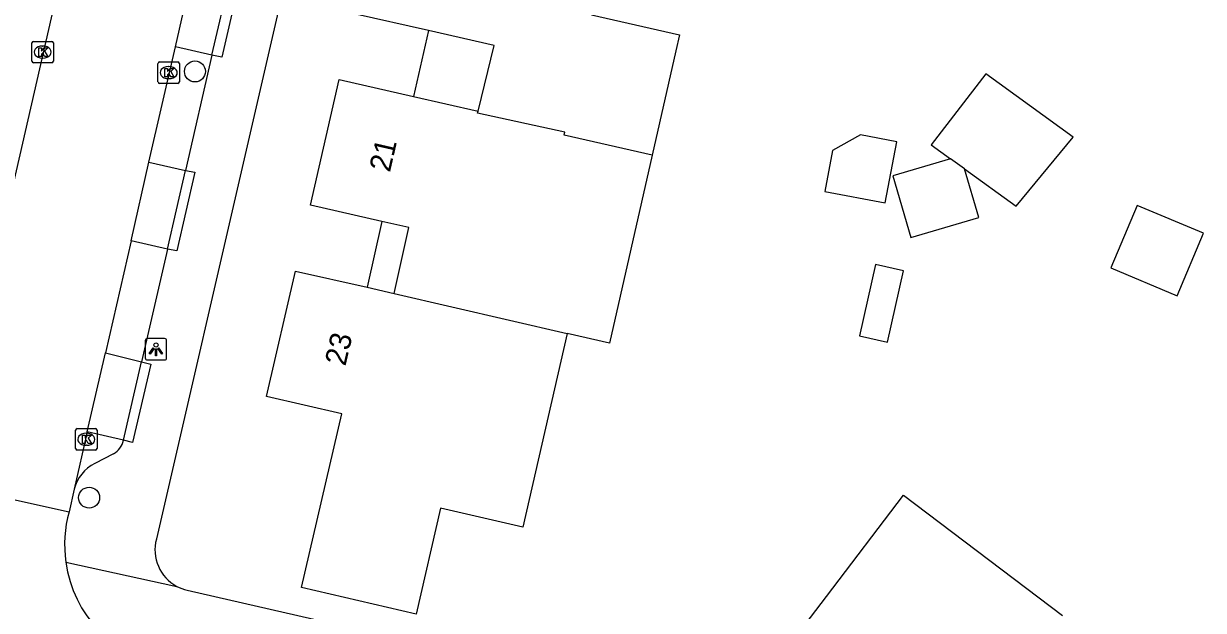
# Model space of a CAD drawing. Extents: x 159628 to 160723, y 388176 to 389416.
# Drawn here: x 160301.6 to 160356.7, y 388567 to 388594.4 of the extents above; entities that cross this region are included whole.
import ezdxf

# ---------------------------------------------------------------- set-up
doc = ezdxf.new("R2010")
doc.units = 0
for name, color, linetype in [('IMGEO_Boom', 7, 'Continuous'), ('IMGEO_Kolk', 7, 'Continuous'), ('IMGEO_Lichtpunt', 7, 'Continuous'), ('IMGEO_Pand', 7, 'Continuous'), ('IMGEO_Pand_nummerreeks', 7, 'Continuous'), ('IMGEO_Pand_overbouw', 7, 'Continuous'), ('IMGEO_Parkeervlak_open', 7, 'Continuous'), ('IMGEO_Rijbaan_lokaal_open', 7, 'Continuous'), ('IMGEO_Voetpad_open', 7, 'Continuous')]:
    doc.layers.add(name, color=color, linetype=linetype)

msp = doc.modelspace()

# ---------------------------------------------------------------- linework, layer by layer
at = {"layer": 'IMGEO_Boom'}
for centre in [(160309.594, 388592.187), (160304.653, 388572.285)]:
    msp.add_circle(centre, 0.489, dxfattribs=at)
at = {"layer": 'IMGEO_Kolk'}
for p, q in [((160301.982, 388592.665), (160301.982, 388593.517)), ((160302.057, 388593.591), (160302.909, 388593.591)), ((160302.47, 388593.371), (160302.495, 388593.371)), ((160302.983, 388593.517), (160302.983, 388592.665)), ((160302.909, 388592.591), (160302.057, 388592.591)), ((160302.493, 388592.811), (160302.468, 388592.811)), ((160307.944, 388592.631), (160308.796, 388592.631)), ((160307.869, 388591.705), (160307.869, 388592.557)), ((160308.357, 388592.411), (160308.382, 388592.411)), ((160308.87, 388592.557), (160308.87, 388591.705)), ((160308.796, 388591.631), (160307.944, 388591.631)), ((160308.38, 388591.851), (160308.355, 388591.851)), ((160304.095, 388575.51), (160304.947, 388575.51)), ((160304.02, 388574.584), (160304.02, 388575.436)), ((160304.508, 388575.29), (160304.533, 388575.29)), ((160305.021, 388575.436), (160305.021, 388574.584)), ((160304.947, 388574.51), (160304.095, 388574.51)), ((160304.531, 388574.73), (160304.506, 388574.73))]:
    msp.add_line(p, q, dxfattribs=at)
for points in [[(160301.982, 388592.665), (160301.982, 388593.517)], [(160302.057, 388593.591), (160302.909, 388593.591)], [(160302.303, 388593.291), (160302.426, 388593.291), (160302.426, 388593.14), (160302.556, 388593.291), (160302.72, 388593.291), (160302.574, 388593.14), (160302.727, 388592.891), (160302.575, 388592.891), (160302.49, 388593.055), (160302.426, 388592.988), (160302.426, 388592.891), (160302.303, 388592.891), (160302.303, 388593.291)], [(160302.983, 388593.517), (160302.983, 388592.665)], [(160302.909, 388592.591), (160302.057, 388592.591)], [(160307.944, 388592.631), (160308.796, 388592.631)], [(160307.869, 388591.705), (160307.869, 388592.557)], [(160308.19, 388592.331), (160308.313, 388592.331), (160308.313, 388592.18), (160308.443, 388592.331), (160308.607, 388592.331), (160308.461, 388592.18), (160308.614, 388591.931), (160308.462, 388591.931), (160308.377, 388592.095), (160308.313, 388592.028), (160308.313, 388591.931), (160308.19, 388591.931), (160308.19, 388592.331)], [(160308.87, 388592.557), (160308.87, 388591.705)], [(160308.796, 388591.631), (160307.944, 388591.631)], [(160304.095, 388575.51), (160304.947, 388575.51)], [(160304.02, 388574.584), (160304.02, 388575.436)], [(160304.341, 388575.21), (160304.464, 388575.21), (160304.464, 388575.059), (160304.594, 388575.21), (160304.758, 388575.21), (160304.612, 388575.059), (160304.765, 388574.81), (160304.613, 388574.81), (160304.528, 388574.974), (160304.464, 388574.907), (160304.464, 388574.81), (160304.341, 388574.81), (160304.341, 388575.21)], [(160305.021, 388575.436), (160305.021, 388574.584)], [(160304.947, 388574.51), (160304.095, 388574.51)]]:
    msp.add_lwpolyline(points, dxfattribs=at)
for centre, start, end in [((160302.059, 388593.515), 91.552, 178.448), ((160302.059, 388593.515), 91.552, 178.448), ((160302.907, 388593.515), 1.552, 88.448), ((160302.907, 388593.515), 1.552, 88.448), ((160302.059, 388592.667), 181.552, 268.448), ((160302.059, 388592.667), 181.552, 268.448), ((160302.907, 388592.667), 271.552, 358.448), ((160302.907, 388592.667), 271.552, 358.448), ((160307.946, 388592.555), 91.552, 178.448), ((160307.946, 388592.555), 91.552, 178.448), ((160308.794, 388592.555), 1.552, 88.448), ((160308.794, 388592.555), 1.552, 88.448), ((160307.946, 388591.707), 181.552, 268.448), ((160307.946, 388591.707), 181.552, 268.448), ((160308.794, 388591.707), 271.552, 358.448), ((160308.794, 388591.707), 271.552, 358.448), ((160304.097, 388575.434), 91.552, 178.448), ((160304.097, 388575.434), 91.552, 178.448), ((160304.945, 388575.434), 1.552, 88.448), ((160304.945, 388575.434), 1.552, 88.448), ((160304.097, 388574.586), 181.552, 268.448), ((160304.097, 388574.586), 181.552, 268.448), ((160304.945, 388574.586), 271.552, 358.448), ((160304.945, 388574.586), 271.552, 358.448)]:
    msp.add_arc(centre, 0.0765, start, end, dxfattribs=at)
for centre, major_axis, ratio, start_param, end_param in [((160302.469, 388593.091), (-0.387, 0.002), 0.722429, 4.712389, 7.853982), ((160302.494, 388593.091), (-0.39, 0.002), 0.717154, 1.570796, 4.712389), ((160308.356, 388592.131), (-0.387, 0.002), 0.722429, 4.712389, 7.853982), ((160308.381, 388592.131), (-0.39, 0.002), 0.717154, 1.570796, 4.712389), ((160304.507, 388575.01), (-0.387, 0.002), 0.722429, 4.712389, 7.853982), ((160304.532, 388575.01), (-0.39, 0.002), 0.717154, 1.570796, 4.712389)]:
    msp.add_ellipse(centre, major_axis=major_axis, ratio=ratio, start_param=start_param, end_param=end_param, dxfattribs=at)
at = {"layer": 'IMGEO_Lichtpunt'}
for p, q in [((160307.275, 388579.617), (160307.275, 388578.81)), ((160307.275, 388579.617), (160307.275, 388578.81)), ((160308.177, 388579.712), (160307.369, 388579.712)), ((160308.177, 388579.712), (160307.369, 388579.712)), ((160308.271, 388578.81), (160308.271, 388579.617)), ((160308.271, 388578.81), (160308.271, 388579.617)), ((160307.369, 388578.716), (160308.177, 388578.716)), ((160307.369, 388578.716), (160308.177, 388578.716))]:
    msp.add_line(p, q, dxfattribs=at)
for points in [[(160307.649, 388579.281), (160307.688, 388579.253), (160307.5, 388578.991), (160307.462, 388579.018), (160307.649, 388579.281)], [(160307.751, 388579.233), (160307.798, 388579.233), (160307.798, 388578.911), (160307.751, 388578.911), (160307.751, 388579.233)], [(160307.861, 388579.253), (160307.899, 388579.28), (160308.086, 388579.018), (160308.047, 388578.99), (160307.861, 388579.253)]]:
    msp.add_lwpolyline(points, dxfattribs=at)
msp.add_circle((160307.774, 388579.415), 0.0994, dxfattribs=at)
for centre, start, end in [((160307.369, 388579.617), 90, 180), ((160307.369, 388579.617), 90, 180), ((160308.177, 388579.617), 0, 90), ((160308.177, 388579.617), 0, 90), ((160307.369, 388578.81), 180, 270), ((160307.369, 388578.81), 180, 270), ((160308.177, 388578.81), 270, 0), ((160308.177, 388578.81), 270, 360)]:
    msp.add_arc(centre, 0.0946, start, end, dxfattribs=at)
at = {"layer": 'IMGEO_Pand'}
for points in [[(160322.818, 388590.336), (160323.576, 388593.398), (160320.496, 388594.097), (160317.032, 388594.883), (160318.353, 388600.624)], [(160328.87, 388598.185), (160328.11, 388594.83), (160332.217, 388593.899), (160332.048, 388593.153), (160330.943, 388588.276)], [(160345.534, 388587.635), (160347.948, 388585.89), (160350.606, 388589.124), (160346.534, 388592.07), (160343.971, 388588.765), (160344.882, 388588.106)], [(160318.891, 388581.823), (160319.59, 388584.899), (160318.33, 388585.185), (160314.987, 388585.943), (160316.335, 388591.808), (160319.797, 388591.022), (160322.818, 388590.336)], [(160330.943, 388588.276), (160326.835, 388589.207), (160326.868, 388589.353), (160322.795, 388590.236), (160322.818, 388590.336)], [(160339.368, 388588.495), (160339.006, 388586.586), (160341.828, 388586.049), (160342.37, 388588.898), (160340.676, 388589.22), (160339.368, 388588.495)], [(160330.943, 388588.276), (160328.954, 388579.498), (160326.979, 388579.946)], [(160344.882, 388588.106), (160342.188, 388587.314), (160343.035, 388584.436), (160346.201, 388585.367), (160345.534, 388587.635)], [(160345.534, 388587.635), (160344.882, 388588.106)], [(160352.375, 388583.013), (160355.47, 388581.716), (160356.691, 388584.629), (160353.596, 388585.926), (160352.375, 388583.013)], [(160326.979, 388579.946), (160324.9, 388570.91), (160321.068, 388571.791), (160319.926, 388566.851), (160314.577, 388568.087), (160316.453, 388576.202), (160312.935, 388577.015), (160314.288, 388582.868), (160317.631, 388582.109), (160318.891, 388581.823)], [(160340.626, 388579.847), (160341.931, 388579.551), (160342.683, 388582.869), (160341.378, 388583.165), (160340.626, 388579.847)], [(160318.891, 388581.823), (160326.979, 388579.946)], [(160344.024, 388558.754), (160341.416, 388560.742), (160339.734, 388561.999), (160339.207, 388561.307), (160336.06, 388563.69), (160339.086, 388567.672), (160342.683, 388572.406), (160350.105, 388566.777)]]:
    msp.add_lwpolyline(points, dxfattribs=at)
at = {"layer": 'IMGEO_Pand_overbouw'}
for points in [[(160320.496, 388594.097), (160319.797, 388591.022), (160322.818, 388590.336), (160323.576, 388593.398)], [(160318.33, 388585.185), (160317.631, 388582.109), (160318.891, 388581.823), (160319.59, 388584.899)]]:
    msp.add_lwpolyline(points, close=True, dxfattribs=at)
at = {"layer": 'IMGEO_Parkeervlak_open'}
for points in [[(160310.391, 388592.943), (160308.679, 388593.335)], [(160307.447, 388587.95), (160309.152, 388587.558)], [(160308.309, 388583.896), (160306.609, 388584.285)], [(160305.412, 388579.05), (160307.098, 388578.632)], [(160306.254, 388574.966), (160304.566, 388575.352)]]:
    msp.add_lwpolyline(points, dxfattribs=at)
at = {"layer": 'IMGEO_Rijbaan_lokaal_open'}
for points in [[(160303.554, 388597.63), (160297.886, 388572.91)], [(160308.679, 388593.335), (160309.517, 388596.998)], [(160307.447, 388587.95), (160308.679, 388593.335)], [(160306.609, 388584.285), (160307.447, 388587.95)], [(160306.609, 388584.285), (160305.412, 388579.05)], [(160304.566, 388575.352), (160305.412, 388579.05)], [(160304.566, 388575.352), (160303.954, 388572.678)], [(160297.886, 388572.91), (160303.715, 388571.625)], [(160303.954, 388572.678), (160303.715, 388571.625)]]:
    msp.add_lwpolyline(points, dxfattribs=at)
for centre, radius, start, end in [((160309.336, 388570.082), 5.829, 164.65, 188.0157), ((160309.324, 388570.085), 5.818, 188.0673, 258.729)]:
    msp.add_arc(centre, radius, start, end, dxfattribs=at)
at = {"layer": 'IMGEO_Voetpad_open'}
for points in [[(160320.916, 388627.257), (160307.792, 388570.355)], [(160311.233, 388596.603), (160311.69, 388596.505), (160310.843, 388592.851), (160310.391, 388592.943)], [(160310.391, 388592.943), (160311.233, 388596.603)], [(160310.391, 388592.943), (160309.152, 388587.558)], [(160309.152, 388587.558), (160309.591, 388587.478), (160308.752, 388583.804), (160308.309, 388583.896)], [(160308.309, 388583.896), (160309.152, 388587.558)], [(160308.309, 388583.896), (160307.098, 388578.632)], [(160307.098, 388578.632), (160307.538, 388578.523), (160306.679, 388574.859), (160306.254, 388574.966)], [(160306.254, 388574.966), (160307.098, 388578.632)], [(160305.795, 388574.333), (160304.917, 388573.882)], [(160303.564, 388569.269), (160308.747, 388568.142)], [(160309.226, 388567.961), (160322.902, 388564.843)]]:
    msp.add_lwpolyline(points, dxfattribs=at)
for centre, radius, start, end in [((160305.293, 388575.18), 0.985, 300.6679, 347.4389), ((160305.768, 388572.214), 1.872, 117.0281, 165.6639), ((160309.669, 388569.852), 1.943, 165.0091, 241.6753), ((160309.688, 388569.908), 2.001, 241.9503, 256.6495)]:
    msp.add_arc(centre, radius, start, end, dxfattribs=at)

# ---------------------------------------------------------------- texts
at = {"layer": 'IMGEO_Pand_nummerreeks'}
for s, rotation, p in [('21', 77.0571, (160318.698, 388587.446)), ('23', 76.9826, (160316.62, 388578.397))]:
    msp.add_text(s, height=1, rotation=rotation, dxfattribs=at).set_placement(p)

doc.saveas('drawing.dxf')
